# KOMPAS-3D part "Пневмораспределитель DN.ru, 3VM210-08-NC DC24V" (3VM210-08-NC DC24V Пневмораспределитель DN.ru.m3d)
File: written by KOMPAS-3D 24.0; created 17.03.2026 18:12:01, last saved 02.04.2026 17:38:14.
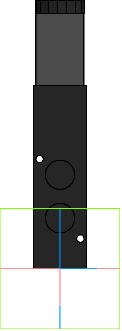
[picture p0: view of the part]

Document properties: Автор: R2D2; Полное имя файла: E:\Работа\Зайцев\Аксессуары для пневмоприводов\Пневмораспределители DN.ru\3VM210-08-NC Пневмораспределитель DN.RU\DC24V\исходные материалы\3VM210-08-NC DC24V Пневмораспределитель DN.ru.m3d

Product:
- Body: Тело 1  | qty 1
    Масса: 0.746454
- Body: Тело 2  | qty 1
    Масса: 0.746454
- Body: Тело 3  | qty 1
    Масса: 0.746454
- Body: Тело 4  | qty 1
    Масса: 0.746454
- Part/product: Пневмораспределитель DN.ru  | designation 3VM210-08-NC DC24V
    Масса: 0.3
    Раздел спецификации: Прочие изделия
    Примечание: D290-00374

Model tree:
1. Тело
2. Элемент выдавливания:1
     Расстояние 2 = 76
3. Отверстия сбоку  (with: Грань.Элемент выдавливания:1)
4. Элемент выдавливания:2
     Расстояние 2 = 1
5. Отверстия сбоку 2  (with: Грань.Элемент выдавливания:1, Ребро.Элемент выдавливания:1)
6. Элемент выдавливания:3
     Расстояние 2 = 22
7. отверстие сверху  (with: Грань.Элемент выдавливания:1)
8. Элемент выдавливания:12
     Расстояние 2 = 5
9. БУ  (with: Грань.Элемент выдавливания:1, Ребро.Элемент выдавливания:1)
10. Элемент выдавливания:4
     Расстояние 1 = 30
11. ЭЛ  (with: Грань.Элемент выдавливания:4, Ребро.Элемент выдавливания:4)
12. Элемент выдавливания:5
     Расстояние 1 = 28.5
13. Пробка  (with: Грань.Элемент выдавливания:4)
14. Элемент выдавливания:6
     Расстояние 1 = 5.5
15. Пробка 2  (with: Грань.Элемент выдавливания:5)
16. Элемент выдавливания:7
     Расстояние 1 = 14
17. головка пробки  (with: Грань.Элемент выдавливания:7, Ребро.Элемент выдавливания:7)
18. Элемент выдавливания:8
     Расстояние 1 = 5
19. Фиксатор  (with: Грань.Элемент выдавливания:1, Ребро.Элемент выдавливания:5)
20. Элемент выдавливания:9
     Расстояние 1 = 2
21. шлиц  (with: Грань.Элемент выдавливания:9, Ребро.Элемент выдавливания:9)
22. Элемент выдавливания:11
     Расстояние 2 = 1
23. отв. снизу  (with: Грань.Элемент выдавливания:1)
24. Элемент выдавливания:10
     Расстояние 2 = 5
25. Эскиз:13  (with: Грань.Элемент выдавливания:1)
26. Элемент выдавливания:13
     Расстояние 2 = 3
27. Эскиз:14  (with: Грань.Элемент выдавливания:13, Ребро.Элемент выдавливания:13)
28. Элемент выдавливания:14
     Расстояние 2 = 32

Expressions: 3VM210-08-NC DC24V; v692/2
